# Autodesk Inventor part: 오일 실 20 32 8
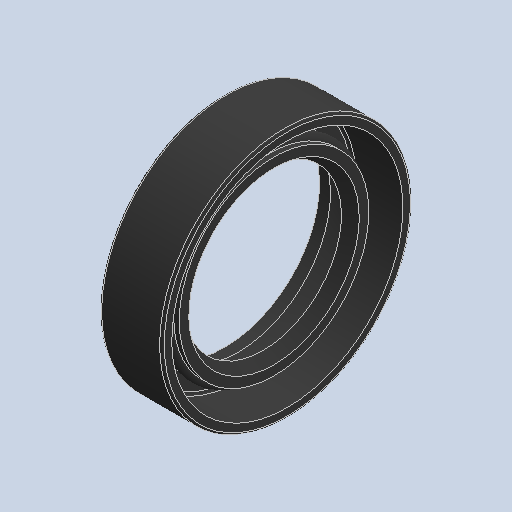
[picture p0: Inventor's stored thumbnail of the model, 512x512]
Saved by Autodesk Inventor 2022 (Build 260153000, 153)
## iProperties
Created: 2024-11
Part Number: 오일 실 20 32 8
Material: 고무
Description: 오일-실
Document SubType Name: Modeling
Designer: PC-12
Density: 0.93 g/cm^3
Appearance: 기본값
Author: jhkim
Sending System: Autodesk Inventor 2025
Preprocessor: ST-DEVELOPER v20
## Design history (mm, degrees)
node "오일 실 20 32 81"
node "솔리드1"
body "Solid1"
